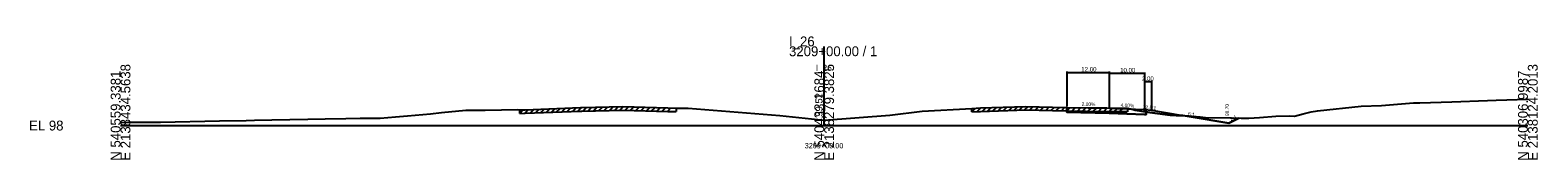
# Model space of a CAD drawing. Extents: x -13101 to 4803, y -924 to 22390.
# Drawn here: x 1974.3 to 2402.8, y 4490.3 to 4525.3 of the extents above; entities that cross this region are included whole.
import ezdxf

# ---------------------------------------------------------------- set-up
doc = ezdxf.new("R2010")
doc.units = 0
for name, color, linetype in [('RD_GPK_XS_Cell', 7, 'Continuous'), ('RD_XD_TX_Width', 7, 'Continuous'), ('RD_XS_Base', 7, 'Continuous'), ('RD_XS_EarthShd', 7, 'Continuous'), ('RD_XS_EwShp', 7, 'Continuous'), ('RD_XS_ExGround', 7, 'Continuous'), ('RD_XS_ExPaveRet', 7, 'Continuous'), ('RD_XS_OSBase', 7, 'Continuous'), ('RD_XS_Pave', 7, 'Continuous'), ('RD_XS_TieSlope', 7, 'Continuous'), ('RD_XS_TX_Baseline', 7, 'Continuous'), ('RD_XS_TX_Elev_EX', 7, 'Continuous'), ('RD_XS_TX_Elev_PR', 7, 'Continuous'), ('RD_XS_TX_ShdSlope', 7, 'Continuous'), ('RD_XS_TX_Slope', 7, 'Continuous'), ('RD_XS_TX_Station', 7, 'Continuous')]:
    doc.layers.add(name, color=color, linetype=linetype)

msp = doc.modelspace()

# ---------------------------------------------------------------- linework, layer by layer
at = {"layer": 'RD_GPK_XS_Cell'}
for p, q in [((2200, 4500), (2200, 4522.51)), ((2000, 4500), (2200, 4500)), ((2200, 4500), (2400, 4500))]:
    msp.add_line(p, q, dxfattribs=at)
at = {"layer": 'RD_XD_TX_Width'}
for p, q in [((2269, 4515.32), (2269, 4505.37)), ((2269, 4515.12), (2281, 4515.12)), ((2281, 4515.32), (2281, 4505.13)), ((2281, 4515.08), (2281, 4505.13)), ((2281, 4514.88), (2291, 4514.88)), ((2291, 4515.08), (2291, 4504.73)), ((2291, 4512.68), (2291, 4504.73)), ((2291, 4512.48), (2293, 4512.48)), ((2293, 4512.68), (2293, 4504.57))]:
    msp.add_line(p, q, dxfattribs=at)
at = {"layer": 'RD_XS_Base'}
for p, q in [((2269, 4503.77), (2281, 4503.53)), ((2281, 4503.53), (2291, 4503.13))]:
    msp.add_line(p, q, dxfattribs=at)
at = {"layer": 'RD_XS_EarthShd'}
msp.add_line((2291, 4504.53), (2293, 4504.37), dxfattribs=at)
at = {"layer": 'RD_XS_EwShp'}
for points in [[(2269, 4504.77), (2269, 4505.17), (2280.35, 4504.99), (2286.1, 4504.95), (2287.14, 4504.72), (2288.34, 4504.36), (2291.5, 4503.88), (2291.5, 4503.11), (2291, 4503.13), (2281, 4503.53), (2269, 4503.77)], [(2293, 4504.37), (2301.92, 4502.88), (2300.02, 4502.9), (2298.35, 4502.92), (2292.6, 4503.72), (2291.5, 4503.88), (2291.5, 4504.11), (2291, 4504.13), (2291, 4504.53)], [(2315.49, 4502.16), (2317.85, 4502.12), (2315, 4500.7), (2301.92, 4502.88), (2302.45, 4502.88), (2306.86, 4502.43), (2308.35, 4502.32)]]:
    msp.add_lwpolyline(points, close=True, dxfattribs=at)
at = {"layer": 'RD_XS_ExGround'}
msp.add_lwpolyline([(2000, 4500.89), (2002.06, 4500.92), (2006.53, 4500.95), (2009.67, 4500.97), (2011.4, 4500.98), (2028.09, 4501.34), (2035.72, 4501.47), (2038.1, 4501.53), (2042.97, 4501.64), (2048.11, 4501.72), (2053.19, 4501.79), (2058.12, 4501.94), (2064, 4502.02), (2068.12, 4502.07), (2072.62, 4502.06), (2073.05, 4502.05), (2073.83, 4502.13), (2078.13, 4502.51), (2081.56, 4502.79), (2088.14, 4503.37), (2091.27, 4503.67), (2098.15, 4504.35), (2103.66, 4504.39), (2112.94, 4504.55), (2113.45, 4504.46), (2114.98, 4504.51), (2130.75, 4505.12), (2131.12, 4505.13), (2142.78, 4505.39), (2155.54, 4505.01), (2157.88, 4504.95), (2161.37, 4504.98), (2187.4, 4502.9), (2200.03, 4501.52), (2218.69, 4502.98), (2227.83, 4504.05), (2241.96, 4504.88), (2244.41, 4505.02), (2257.29, 4505.45), (2268.7, 4505.17), (2280.35, 4504.99), (2286.1, 4504.95), (2287.14, 4504.72), (2288.34, 4504.36), (2292.6, 4503.72), (2298.35, 4502.92), (2300.02, 4502.9), (2302.45, 4502.88), (2306.86, 4502.43), (2308.35, 4502.32), (2315.49, 4502.16), (2318.52, 4502.11), (2320.73, 4502.14), (2323.7, 4502.31), (2328.37, 4502.63), (2332.22, 4502.73), (2333.72, 4502.62), (2336.1, 4503.3), (2338.38, 4503.93), (2340.25, 4504.19), (2352.61, 4505.51), (2358.4, 4505.72), (2367.51, 4506.41), (2369.25, 4506.46), (2378.42, 4506.76), (2388.54, 4507.14), (2390.95, 4507.21), (2400, 4507.5)], dxfattribs=at)
at = {"layer": 'RD_XS_ExPaveRet'}
for p, q in [((2113.45, 4503.46), (2114.48, 4504.49)), ((2113.45, 4503.46), (2113.45, 4504.46)), ((2114.95, 4503.5), (2115.99, 4504.54)), ((2114.98, 4503.51), (2130.75, 4504.12)), ((2116.45, 4503.56), (2117.49, 4504.6)), ((2117.95, 4503.62), (2118.99, 4504.66)), ((2119.45, 4503.68), (2120.49, 4504.72)), ((2120.95, 4503.74), (2121.99, 4504.78)), ((2122.45, 4503.8), (2123.49, 4504.84)), ((2123.95, 4503.85), (2124.99, 4504.89)), ((2125.45, 4503.91), (2126.49, 4504.95)), ((2126.95, 4503.97), (2127.99, 4505.01)), ((2128.45, 4504.03), (2129.49, 4505.07)), ((2129.95, 4504.09), (2130.99, 4505.13)), ((2130.75, 4504.12), (2131.12, 4504.13)), ((2131.12, 4504.13), (2142.78, 4504.39)), ((2131.45, 4504.14), (2132.47, 4505.16)), ((2132.95, 4504.17), (2133.97, 4505.2)), ((2134.45, 4504.21), (2135.47, 4505.23)), ((2135.95, 4504.24), (2136.97, 4505.26)), ((2137.45, 4504.27), (2138.47, 4505.3)), ((2138.95, 4504.31), (2139.97, 4505.33)), ((2140.45, 4504.34), (2141.47, 4505.36)), ((2141.95, 4504.37), (2142.96, 4505.39)), ((2142.78, 4504.39), (2155.54, 4504.01)), ((2143.45, 4504.37), (2144.42, 4505.34)), ((2144.95, 4504.33), (2145.92, 4505.3)), ((2146.45, 4504.28), (2147.42, 4505.25)), ((2147.95, 4504.24), (2148.92, 4505.21)), ((2149.45, 4504.19), (2150.42, 4505.16)), ((2150.95, 4504.15), (2151.92, 4505.12)), ((2152.45, 4504.1), (2153.42, 4505.07)), ((2153.95, 4504.06), (2154.92, 4505.03)), ((2155.45, 4504.01), (2156.42, 4504.99)), ((2155.54, 4504.01), (2157.88, 4503.95)), ((2157.88, 4504.95), (2157.88, 4503.95)), ((2241.96, 4503.88), (2243.02, 4504.94)), ((2241.96, 4503.88), (2241.96, 4504.88)), ((2241.96, 4503.88), (2244.41, 4504.02)), ((2243.46, 4503.97), (2244.52, 4505.03)), ((2244.41, 4504.02), (2257.29, 4504.45)), ((2244.96, 4504.04), (2246, 4505.08)), ((2246.46, 4504.09), (2247.5, 4505.13)), ((2247.96, 4504.14), (2249, 4505.17)), ((2249.46, 4504.19), (2250.5, 4505.22)), ((2250.96, 4504.24), (2252, 4505.27)), ((2252.46, 4504.29), (2253.5, 4505.32)), ((2253.96, 4504.34), (2255, 4505.37)), ((2255.46, 4504.39), (2256.5, 4505.42)), ((2256.96, 4504.44), (2257.96, 4505.43)), ((2257.29, 4504.45), (2268.7, 4504.17)), ((2258.46, 4504.42), (2259.44, 4505.39)), ((2259.96, 4504.38), (2260.94, 4505.36)), ((2261.46, 4504.35), (2262.44, 4505.32)), ((2262.96, 4504.31), (2263.94, 4505.29)), ((2264.46, 4504.27), (2265.44, 4505.25)), ((2265.96, 4504.24), (2266.94, 4505.22)), ((2267.46, 4504.2), (2268.44, 4505.18)), ((2268.7, 4504.17), (2280.35, 4503.99)), ((2268.96, 4504.17), (2269.95, 4505.15)), ((2270.46, 4504.15), (2271.45, 4505.13)), ((2271.96, 4504.12), (2272.95, 4505.11)), ((2273.46, 4504.1), (2274.45, 4505.08)), ((2274.96, 4504.07), (2275.95, 4505.06)), ((2276.46, 4504.05), (2277.45, 4505.03)), ((2277.96, 4504.03), (2278.95, 4505.01)), ((2279.46, 4504), (2280.45, 4504.99)), ((2280.35, 4503.99), (2286.1, 4503.95)), ((2280.96, 4503.98), (2281.96, 4504.98)), ((2282.46, 4503.97), (2283.46, 4504.97)), ((2283.96, 4503.97), (2284.96, 4504.96)), ((2286.1, 4503.95), (2286.17, 4503.93)), ((2286.17, 4504.93), (2286.17, 4503.93)), ((2113.45, 4503.46), (2114.98, 4503.51))]:
    msp.add_line(p, q, dxfattribs=at)
at = {"layer": 'RD_XS_OSBase'}
for p, q in [((2269, 4504.77), (2269, 4505.17)), ((2269, 4503.77), (2269, 4504.77)), ((2291, 4504.13), (2291, 4504.53)), ((2291.5, 4504.11), (2291, 4504.13)), ((2291.5, 4503.11), (2291.5, 4504.11)), ((2291, 4503.13), (2291.5, 4503.11))]:
    msp.add_line(p, q, dxfattribs=at)
at = {"layer": 'RD_XS_Pave'}
for p, q in [((2269, 4505.17), (2281, 4504.93)), ((2281, 4504.93), (2291, 4504.53))]:
    msp.add_line(p, q, dxfattribs=at)
at = {"layer": 'RD_XS_TieSlope'}
for p, q in [((2293, 4504.37), (2315, 4500.7)), ((2315, 4500.7), (2317.85, 4502.12))]:
    msp.add_line(p, q, dxfattribs=at)

# ---------------------------------------------------------------- texts
at = {"layer": 'RD_GPK_XS_Cell'}
for s, p in [('I_26', (2190, 4522.51)), ('3209+00.00 / 1', (2190, 4519.71)), ('EL 98', (1974, 4498.6))]:
    msp.add_text(s, height=2.8, dxfattribs=at).set_placement(p)
for s, p in [('E 2138434.5638', (2002.8, 4490)), ('E 2138279.3825', (2202.8, 4490)), ('E 2138124.2013', (2402.8, 4490)), ('N 540559.3381', (2000, 4490)), ('N 540433.1684', (2200, 4490)), ('N 540306.9987', (2400, 4490))]:
    msp.add_text(s, height=2.8, rotation=90, dxfattribs=at).set_placement(p)
at = {"layer": 'RD_XD_TX_Width'}
for s, p in [('12.00', (2273.07, 4515.37)), ('10.00', (2284.11, 4515.13)), ('2.00', (2290.31, 4512.73))]:
    msp.add_text(s, height=1.25, dxfattribs=at).set_placement(p)
at = {"layer": 'RD_XS_TX_Baseline'}
msp.add_text('I_26', height=1.75, dxfattribs=at).set_placement((2197.6, 4515.52))
at = {"layer": 'RD_XS_TX_Elev_EX'}
msp.add_text('99.52', height=2, rotation=90, dxfattribs=at).set_placement((2199.5, 4502.52))
at = {"layer": 'RD_XS_TX_Elev_PR'}
msp.add_text('98.70', height=1, rotation=90, dxfattribs=at).set_placement((2315, 4502.7))
at = {"layer": 'RD_XS_TX_ShdSlope'}
msp.add_text('12.5:1', height=1, rotation=355.4261, dxfattribs=at).set_placement((2290.51, 4504.82))
msp.add_text('12.5:1', height=1, rotation=355.4261, dxfattribs=at).set_placement((2290.51, 4504.82))
at = {"layer": 'RD_XS_TX_Slope'}
for s, rotation, p in [('2.00%', 358.8542, (2273.16, 4505.59)), ('4.00%', 357.7094, (2284.22, 4505.3)), ('6:1', 350.5377, (2303.35, 4502.9)), ('2:1', 26.5651, (2315.64, 4501.3))]:
    msp.add_text(s, height=1, rotation=rotation, dxfattribs=at).set_placement(p)
at = {"layer": 'RD_XS_TX_Station'}
msp.add_text('3209+00.00', height=1.5, dxfattribs=at).set_placement((2194.45, 4493.52))

doc.saveas('drawing.dxf')
